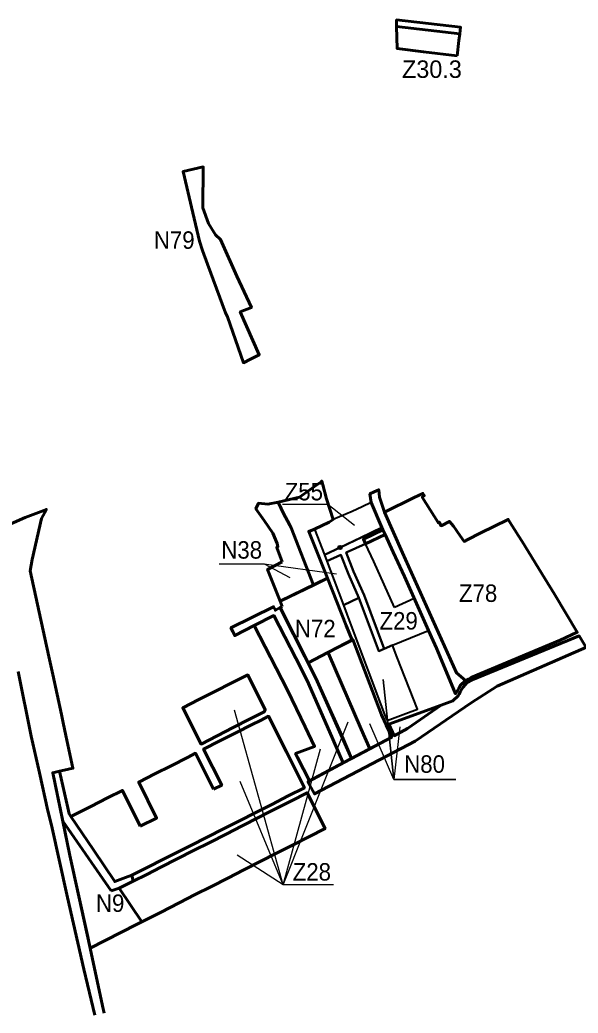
# Model space of a CAD drawing. Extents: x -650277 to -643425, y -1073980 to -1066720.
# Drawn here: x -648765 to -647999, y -1068122 to -1066758 of the extents above; entities that cross this region are included whole.
import ezdxf

# ---------------------------------------------------------------- set-up
doc = ezdxf.new("R2010")
doc.units = 0
doc.header["$LTSCALE"] = 9.6
doc.header["$PDMODE"] = 32
doc.header["$PDSIZE"] = 4.8
for name, color, linetype, lineweight in [('1', 7, 'Continuous', 60), ('15', 7, 'Continuous', 60), ('2', 7, 'Continuous', 40), ('3', 7, 'Continuous', 60), ('45', 7, 'Continuous', 60), ('48', 7, 'Continuous', 60), ('59', 7, 'Continuous', 25), ('63', 7, 'Continuous', 25), ('7', 7, 'Continuous', 60), ('9', 7, 'Continuous', 60)]:
    doc.layers.add(name, color=color, linetype=linetype, lineweight=lineweight)

msp = doc.modelspace()

# ---------------------------------------------------------------- linework, layer by layer
at = {"layer": '1'}
msp.add_line((-648609.91, -1067940.58), (-648611.61, -1067932.63), dxfattribs=at)
for points in [[(-648397.98, -1067678.79), (-648373.99, -1067728.95), (-648361.08, -1067755.88), (-648387.04, -1067765.67), (-648384.25, -1067771.07), (-648367.811, -1067802.994), (-648321.623, -1067778.399), (-648326, -1067769), (-648337.32, -1067742.59), (-648348.55, -1067716.71), (-648359.6, -1067691.58), (-648371.34, -1067665.08), (-648386.91, -1067634.83), (-648402.02, -1067605.49), (-648417.12, -1067576.17), (-648443.83, -1067589.92), (-648428.7, -1067619.24), (-648413.57, -1067648.57)], [(-648342.697, -1067626.806), (-648369.949, -1067640.851), (-648359.213, -1067661.956), (-648310.511, -1067772.476), (-648285.254, -1067759.008), (-648296.891, -1067732.172), (-648342.023, -1067628.096)], [(-648519.63, -1067691.58), (-648541.86, -1067702.86), (-648516.73, -1067752.57), (-648494.84, -1067741.06), (-648472.5, -1067729.76), (-648450.23, -1067718.32), (-648430.17, -1067708.33), (-648428.67, -1067705.52), (-648452.72, -1067657.62)]]:
    msp.add_lwpolyline(points, close=True, dxfattribs=at)
for points in [[(-648399.64, -1067763.26), (-648424.14, -1067714.34), (-648435.34, -1067720.01), (-648446.58, -1067725.71), (-648468.97, -1067736.91), (-648480.06, -1067742.47), (-648491.14, -1067748.02), (-648513.23, -1067759.38), (-648488.49, -1067808.76), (-648499.7, -1067814.37)], [(-648611.61, -1067932.63), (-648547.09, -1067899.87), (-648530.81, -1067891.61), (-648508.22, -1067880.38), (-648486.09, -1067868.98), (-648463.91, -1067857.74), (-648441.47, -1067846.37), (-648419.44, -1067835.3), (-648397.04, -1067823.85), (-648374.84, -1067812.43), (-648399.64, -1067763.26)], [(-648499.7, -1067814.37), (-648524.44, -1067765.11), (-648535.61, -1067770.85), (-648557.84, -1067782.26), (-648580.14, -1067793.61), (-648602.3, -1067804.83), (-648577.78, -1067854.07), (-648600.14, -1067865.29)], [(-648600.14, -1067865.29), (-648624.76, -1067816.11), (-648645.11, -1067826.48), (-648668.085, -1067838.186), (-648675.26, -1067841.84), (-648695.27, -1067852.04), (-648664.41, -1067897.91)], [(-648572.5, -1067983.59), (-648546.76, -1067970.44), (-648524.72, -1067958.93), (-648502.59, -1067948), (-648480.12, -1067936.55), (-648457.87, -1067925.4), (-648435.55, -1067913.84), (-648413.41, -1067902.53), (-648402.29, -1067897.02), (-648391.08, -1067891.24), (-648368.78, -1067879.75), (-648346.57, -1067868.56), (-648371.27, -1067819.47), (-648393.35, -1067830.81), (-648415.69, -1067841.98), (-648426.65, -1067847.64), (-648437.89, -1067853.4), (-648460.33, -1067864.88), (-648482.5, -1067876.22), (-648504.92, -1067887.52), (-648527.33, -1067898.74), (-648549.44, -1067910.07), (-648571.88, -1067921.71), (-648591.04, -1067931.62), (-648609.91, -1067940.58)], [(-648664.41, -1067897.91), (-648635.249, -1067941.252), (-648620.658, -1067935.93), (-648611.61, -1067932.63)], [(-648609.91, -1067940.58), (-648629.22, -1067950.214), (-648597.93, -1067996.72), (-648572.5, -1067983.59)]]:
    msp.add_lwpolyline(points, dxfattribs=at)
at = {"layer": '1', "lineweight": 25}
msp.add_lwpolyline([(-648335, -1067946), (-648404, -1067946), (-648353, -1067759)], dxfattribs=at)
at = {"layer": '15'}
msp.add_line((-648264.34, -1067464.83), (-648267.21, -1067458.61), dxfattribs=at)
for points in [[(-648161.58, -1066777.41), (-648160.51, -1066768.4), (-648248.43, -1066758.34), (-648248.77, -1066767.43)], [(-648362.585, -1067534.204), (-648343.41, -1067524.81), (-648369.01, -1067460.52), (-648361, -1067457.36), (-648341.15, -1067448.14), (-648335.38, -1067444.07), (-648344.41, -1067416.04), (-648349.67, -1067396.88), (-648351.06, -1067391.62), (-648352.16, -1067392.42), (-648353.35, -1067393.29), (-648381.48, -1067413.68), (-648410.92, -1067420.63), (-648409.61, -1067423.44), (-648404.29, -1067434.9), (-648394.92, -1067452.23), (-648393.17, -1067455.88)], [(-648237.81, -1067522.42), (-648204.88, -1067596.54), (-648198.39, -1067610.97), (-648193.8, -1067621), (-648189.03, -1067631.71), (-648167.48, -1067683.45), (-648164.79, -1067678.96), (-648163.11, -1067676.17), (-648160.68, -1067671.55), (-648153.98, -1067665.43), (-648166.173, -1067654.853), (-648240.51, -1067489.9), (-648265.197, -1067434.03), (-648265.197, -1067434.03), (-648272.022, -1067413.59), (-648273.008, -1067403.338), (-648279.24, -1067406.38), (-648285.08, -1067409.24), (-648283.21, -1067420.88), (-648268.67, -1067455.43), (-648267.21, -1067458.61), (-648264.34, -1067464.83), (-648253.1, -1067489.23)], [(-648359.6, -1067691.58), (-648348.55, -1067716.71), (-648337.32, -1067742.59), (-648326, -1067769), (-648321.623, -1067778.399), (-648310.511, -1067772.476), (-648323.178, -1067741.953), (-648359.213, -1067661.956), (-648405.054, -1067571.837), (-648408.002, -1067565.219), (-648414.73, -1067568.8), (-648417.19, -1067564.02), (-648475.78, -1067593.11), (-648473.34, -1067598.06), (-648470.57, -1067603.69), (-648470.47, -1067603.64), (-648443.83, -1067589.92), (-648417.12, -1067576.17), (-648402.02, -1067605.49), (-648386.91, -1067634.83), (-648371.34, -1067665.08)], [(-647988.235, -1067619.912), (-647995.04, -1067608.56), (-647997.68, -1067604.11), (-648144.83, -1067664.48), (-648151.6, -1067668.12), (-648157.2, -1067674.32), (-648161, -1067680.96), (-648162.69, -1067684), (-648164.09, -1067686.51), (-648171.21, -1067693.37), (-648187.139, -1067699.179), (-648233.264, -1067731.288), (-648251.711, -1067741.124), (-648258.96, -1067725.37), (-648262.632, -1067726.711), (-648255.016, -1067742.886), (-648319.983, -1067777.526), (-648370.113, -1067804.22), (-648360.993, -1067821.027), (-648222.872, -1067748.412), (-648146.127, -1067695.8), (-648110.36, -1067673.133), (-647988.052, -1067619.624)]]:
    msp.add_lwpolyline(points, close=True, dxfattribs=at)
for points in [[(-648793.71, -1067456.88), (-648757.97, -1067441.51), (-648728.95, -1067430.33), (-648735.59, -1067442.88), (-648748.53, -1067499.3), (-648751.29, -1067514.57), (-648731.06, -1067607.06), (-648725.8, -1067632.36), (-648720.1, -1067657.12), (-648708.26, -1067712.07), (-648706.08, -1067723.56), (-648702.33, -1067740.84), (-648692.53, -1067785.79), (-648704.614, -1067788.491), (-648710.961, -1067789.906), (-648720.34, -1067792), (-648696.93, -1067905.76), (-648672.31, -1068017.25), (-648668.92, -1068032.96), (-648651.89, -1068111.95), (-648649.74, -1068121.95)], [(-648267.21, -1067458.61), (-648294.04, -1067471.35), (-648291.172, -1067477.571), (-648264.34, -1067464.83)], [(-648662.71, -1068124.76), (-648677.61, -1068061.74), (-648700.16, -1067963.42), (-648722.09, -1067863.84), (-648727.05, -1067844.33), (-648738.7, -1067792.04), (-648749.97, -1067741.49), (-648767.84, -1067652.98)], [(-648710.961, -1067789.906), (-648720.34, -1067792), (-648706.687, -1067858.345), (-648640, -1067954)], [(-648695.27, -1067852.04), (-648697.7, -1067848.43), (-648699.621, -1067840.06), (-648699.593, -1067840.046), (-648710.96, -1067789.91)], [(-648611.61, -1067932.63), (-648620.658, -1067935.93), (-648635.249, -1067941.252), (-648664.41, -1067897.91), (-648695.27, -1067852.04)], [(-648640, -1067954), (-648629.22, -1067950.214), (-648609.91, -1067940.58), (-648611.61, -1067932.63)]]:
    msp.add_lwpolyline(points, dxfattribs=at)
at = {"layer": '2'}
msp.add_line((-648347.51, -1067492.87), (-648326.09, -1067482.7), dxfattribs=at)
for points in [[(-648268.67, -1067455.43), (-648283.21, -1067420.88), (-648295.66, -1067426.76), (-648309.57, -1067433.34), (-648335.38, -1067444.07), (-648341.15, -1067448.14)], [(-648341.15, -1067448.14), (-648361, -1067457.36), (-648347.51, -1067492.87)], [(-648268.67, -1067455.43), (-648297.915, -1067469.319), (-648326.09, -1067482.7), (-648347.51, -1067492.87), (-648344.186, -1067501.627), (-648324.735, -1067492.8), (-648314.647, -1067519.171), (-648300.258, -1067551.772), (-648300.258, -1067551.772), (-648272.941, -1067624.811), (-648265.601, -1067621.762), (-648292.991, -1067548.356), (-648307.57, -1067515.44), (-648317.435, -1067489.488), (-648291.172, -1067477.571), (-648294.04, -1067471.35)], [(-648326.09, -1067482.7), (-648295.409, -1067468.129), (-648268.67, -1067455.43)], [(-648294.04, -1067471.35), (-648267.21, -1067458.61), (-648268.67, -1067455.43)], [(-648314.647, -1067519.171), (-648324.735, -1067492.8), (-648344.186, -1067501.627)], [(-648344.186, -1067501.627), (-648334.09, -1067528.2), (-648321.36, -1067561.69)], [(-648321.36, -1067561.69), (-648300.258, -1067551.772), (-648314.647, -1067519.171)], [(-648254.04, -1067616.96), (-648265.601, -1067621.762), (-648272.941, -1067624.811), (-648300.258, -1067551.772), (-648300.258, -1067551.772), (-648321.36, -1067561.69)], [(-648321.36, -1067561.69), (-648311.95, -1067586.45), (-648265.08, -1067712.06)], [(-648265.08, -1067712.06), (-648261.25, -1067720.39), (-648235.78, -1067710.79), (-648219.86, -1067704.42), (-648247.53, -1067633.53), (-648254.04, -1067616.96)]]:
    msp.add_lwpolyline(points, dxfattribs=at)
for points in [[(-648251.33, -1067565.28), (-648279.86, -1067502.11), (-648291.17, -1067477.57), (-648317.435, -1067489.488), (-648307.57, -1067515.44), (-648292.991, -1067548.356), (-648265.601, -1067621.762), (-648254.04, -1067616.96), (-648204.88, -1067596.54), (-648224.16, -1067552.55)], [(-648324.735, -1067492.8), (-648344.186, -1067501.627), (-648334.09, -1067528.2), (-648321.36, -1067561.69), (-648300.258, -1067551.772), (-648314.647, -1067519.171)]]:
    msp.add_lwpolyline(points, close=True, dxfattribs=at)
msp.add_point((-648326.09, -1067482.7), dxfattribs=at)
at = {"layer": '3'}
msp.add_lwpolyline([(-648165.33, -1066807.74), (-648162.8, -1066786.8), (-648161.58, -1066777.41), (-648248.77, -1066767.43), (-648247.78, -1066797.53), (-648211.58, -1066802.18)], close=True, dxfattribs=at)
at = {"layer": '45'}
msp.add_lwpolyline([(-648405.41, -1067563.84), (-648408.002, -1067565.219), (-648369.949, -1067640.851), (-648342.697, -1067626.806), (-648328.54, -1067619.51), (-648309.522, -1067609.713), (-648317.43, -1067590), (-648343.41, -1067524.81), (-648408.26, -1067556.58)], close=True, dxfattribs=at)
at = {"layer": '48'}
for points in [[(-648528.01, -1067023.13), (-648518.72, -1067061.99), (-648514.86, -1067074.83), (-648507.88, -1067093.9), (-648483.31, -1067160.63), (-648480.57, -1067166.13), (-648458.73, -1067229.1), (-648449.03, -1067224.14), (-648437.02, -1067217.99), (-648462.97, -1067159.24), (-648447.66, -1067153.25), (-648467.56, -1067110.02), (-648490.23, -1067060.06), (-648496.87, -1067053.5), (-648506.78, -1067037.81), (-648514.38, -1067016.2), (-648513.842, -1066960.243), (-648541.52, -1066966.657)], [(-648405.27, -1067502.27), (-648425.5, -1067512.73), (-648408.26, -1067556.58), (-648362.585, -1067534.205), (-648393.17, -1067455.88), (-648394.92, -1067452.23), (-648404.29, -1067434.9), (-648410.92, -1067420.63), (-648425, -1067423.05), (-648437.75, -1067421.99), (-648441.48, -1067429.63), (-648430.4, -1067445.51), (-648418.3, -1067462.86), (-648412.46, -1067477.42), (-648411.25, -1067481.73), (-648412.89, -1067482.55)], [(-648342.023, -1067628.096), (-648296.891, -1067732.172), (-648285.254, -1067759.008), (-648255.016, -1067742.886), (-648265.614, -1067720.378), (-648269.27, -1067712.6), (-648308.43, -1067609.15), (-648328.54, -1067619.51), (-648342.697, -1067626.806)], [(-648258.96, -1067725.37), (-648251.711, -1067741.124), (-648233.264, -1067731.288), (-648187.139, -1067699.179)]]:
    msp.add_lwpolyline(points, close=True, dxfattribs=at)
at = {"layer": '59', "lineweight": 35}
for p, q in [((-648267, -1067664), (-648252, -1067801)), ((-648252, -1067801), (-648167, -1067801))]:
    msp.add_line(p, q, dxfattribs=at)
at = {"layer": '59'}
for points in [[(-648405, -1067423), (-648343, -1067423), (-648306, -1067452)], [(-648492, -1067505), (-648430, -1067505), (-648331, -1067519)]]:
    msp.add_lwpolyline(points, dxfattribs=at)
at = {"layer": '63'}
for p, q in [((-648430, -1067505), (-648395, -1067524)), ((-648404, -1067946), (-648471, -1067706)), ((-648404, -1067946), (-648315, -1067722)), ((-648252, -1067801), (-648285, -1067725)), ((-648244, -1067729), (-648252, -1067801)), ((-648404, -1067946), (-648463, -1067804))]:
    msp.add_line(p, q, dxfattribs=at)
msp.add_lwpolyline([(-648335, -1067946), (-648404, -1067946), (-648467, -1067905)], dxfattribs=at)
at = {"layer": '7'}
msp.add_lwpolyline([(-648640, -1067954), (-648706.687, -1067858.345), (-648696.93, -1067905.76), (-648668.92, -1068032.96), (-648605.323, -1068000.463), (-648597.93, -1067996.72), (-648629.22, -1067950.214)], close=True, dxfattribs=at)
at = {"layer": '9'}
msp.add_lwpolyline([(-648153.98, -1067665.43), (-648149.933, -1067663.646), (-648146.21, -1067661.3), (-648023.96, -1067610.13), (-648000.63, -1067599.14), (-648031.77, -1067546.6), (-648045.04, -1067525.15), (-648076.32, -1067474.6), (-648081.31, -1067466.54), (-648095.28, -1067444.06), (-648133.56, -1067463.2), (-648150.46, -1067471.66), (-648155.85, -1067474.35), (-648164.24, -1067462.15), (-648166.97, -1067458.18), (-648170.38, -1067453.23), (-648175.94, -1067446.89), (-648187.44, -1067452.8), (-648190.23, -1067447.83), (-648191.46, -1067448.59), (-648213.34, -1067413.46), (-648210.48, -1067411.68), (-648211.08, -1067410.6), (-648212.32, -1067408.39), (-648224.19, -1067414.14), (-648265.197, -1067434.03), (-648240.51, -1067489.9), (-648240.51, -1067489.9), (-648166.173, -1067654.853)], close=True, dxfattribs=at)

# ---------------------------------------------------------------- texts
at = {"layer": '59', "width": 0.95}
for s, p in [('Z55', (-648402, -1067418)), ('N38', (-648489, -1067498)), ('Z29', (-648271.915, -1067595.341)), ('N80', (-648238, -1067792))]:
    msp.add_text(s, height=24, dxfattribs=at).set_placement(p)
at = {"layer": '63'}
msp.add_text('Z30.3', height=24, dxfattribs=at).set_placement((-648241, -1066838))
at = {"layer": '63', "width": 0.95}
for s, p in [('N79', (-648581.544, -1067072.648)), ('Z78', (-648162.836, -1067557.421)), ('N72', (-648388, -1067606)), ('Z28', (-648391, -1067940)), ('N9', (-648661, -1067983))]:
    msp.add_text(s, height=24, dxfattribs=at).set_placement(p)

doc.saveas('drawing.dxf')
